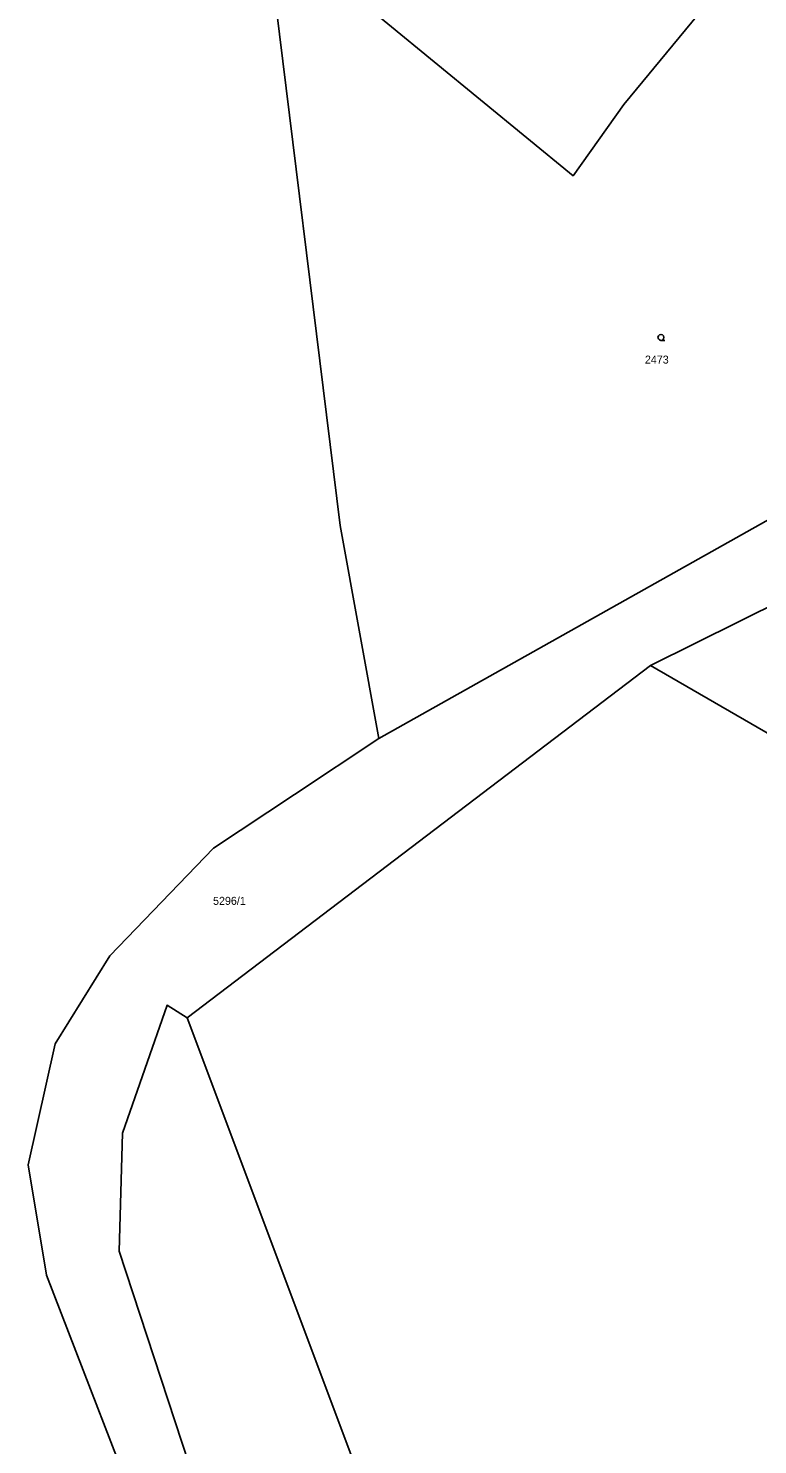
# Model space of a CAD drawing. Extents: x -439750 to -439180, y -1258684 to -1258308.
# Drawn here: x -439666.8 to -439630.4, y -1258510.9 to -1258440.1 of the extents above; entities that cross this region are included whole.
import ezdxf

# ---------------------------------------------------------------- set-up
doc = ezdxf.new("R2010")
doc.units = 0
doc.layers.add('KATASTER', color=7, linetype='Continuous')
doc.layers.add('UOV', color=7, linetype='Continuous')

# ---------------------------------------------------------------- blocks, each defined once
blk = doc.blocks.new('304')
blk.add_lwpolyline([(0, 0), (-0.38, 0.1), (-0.65, 0.37), (-0.75, 0.74), (-0.65, 1.11), (-0.38, 1.38), (-0.01, 1.48), (0.36, 1.38), (0.63, 1.11), (0.73, 0.73), (0.63, 0.35), (0.36, 0.08), (-0.02, -0.02), (0.98, -0.02)])

msp = doc.modelspace()

# ---------------------------------------------------------------- linework, layer by layer
at = {"layer": 'KATASTER'}
for points in [[(-439660.49, -1258516.44), (-439665.91, -1258502.4), (-439666.82, -1258496.88), (-439665.48, -1258490.84), (-439662.74, -1258486.44), (-439657.56, -1258481.06), (-439653.51, -1258478.38), (-439649.29, -1258475.58), (-439627.78, -1258463.49), (-439610.82, -1258457.46), (-439604.91, -1258457.14), (-439594.1, -1258457.31), (-439586.76, -1258455.52), (-439579.1, -1258452.12), (-439572.34, -1258446.7), (-439567.09, -1258440.4), (-439566.51, -1258439.64), (-439564.85, -1258437.53), (-439556.57, -1258427.01), (-439547.65, -1258418.05), (-439537.73, -1258410.35)], [(-439536.05, -1258413.64), (-439546.05, -1258421.31), (-439554.71, -1258430.36), (-439570.11, -1258449.98), (-439574.47, -1258453.63), (-439580.2, -1258456.85), (-439586.86, -1258459.56), (-439593.42, -1258460.84), (-439598.86, -1258460.62), (-439604.63, -1258460.39), (-439610.67, -1258460.8), (-439615.1, -1258461.87), (-439623.26, -1258465.49), (-439629.03, -1258468.61), (-439635.72, -1258471.93), (-439658.88, -1258489.54), (-439659.88, -1258488.91), (-439662.11, -1258495.3), (-439662.28, -1258501.2), (-439658.45, -1258512.88)]]:
    msp.add_lwpolyline(points, dxfattribs=at)
for points in [[(-439654.95, -1258434.81), (-439653.48, -1258436.02), (-439639.58, -1258447.44), (-439637.04, -1258443.88), (-439631.52, -1258437.16), (-439625.47, -1258430.92), (-439614.4, -1258450.89), (-439627.78, -1258463.49), (-439649.29, -1258475.58), (-439651.22, -1258464.92)], [(-439635.72, -1258471.93), (-439629.03, -1258468.61), (-439601.7, -1258475.86), (-439597.79, -1258476.9), (-439591.18, -1258477.49), (-439591.03, -1258485.49), (-439606.15, -1258484.83), (-439620.34, -1258480.81)], [(-439658.88, -1258489.54), (-439635.72, -1258471.93), (-439620.34, -1258480.81), (-439606.15, -1258484.83), (-439591.03, -1258485.49), (-439564.69, -1258504.32), (-439589.36, -1258506.21), (-439597.08, -1258522.38), (-439597.45, -1258561.13), (-439640.46, -1258538.63)]]:
    msp.add_lwpolyline(points, close=True, dxfattribs=at)
at = {"layer": 'UOV'}
for points in [[(-439649.29, -1258475.58), (-439627.78, -1258463.49), (-439618.9, -1258463.55), (-439623.26, -1258465.49), (-439629.03, -1258468.61), (-439635.72, -1258471.93), (-439658.88, -1258489.54), (-439659.88, -1258488.91), (-439662.11, -1258495.3), (-439662.28, -1258501.2), (-439658.45, -1258512.88), (-439640.46, -1258538.63), (-439645.84, -1258537.45), (-439648.8, -1258533.92), (-439660.49, -1258516.44), (-439665.91, -1258502.4), (-439666.82, -1258496.88), (-439665.48, -1258490.84), (-439662.74, -1258486.44), (-439657.56, -1258481.06), (-439653.51, -1258478.38)], [(-439629.03, -1258468.61), (-439597.79, -1258476.9), (-439591.18, -1258477.49), (-439591.03, -1258485.49), (-439606.15, -1258484.83), (-439620.34, -1258480.81), (-439635.72, -1258471.93)]]:
    msp.add_lwpolyline(points, close=True, dxfattribs=at)

# ---------------------------------------------------------------- block references
at = {"layer": 'KATASTER', "xscale": 0.2, "yscale": 0.20000000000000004}
msp.add_blockref('304', (-439635.19, -1258455.67), dxfattribs=at)

# ---------------------------------------------------------------- texts
at = {"layer": 'KATASTER'}
msp.add_text('2473', height=0.4, dxfattribs=at).set_placement((-439635.992, -1258456.83))
at = {"layer": 'UOV'}
msp.add_text('5296/1', height=0.4, dxfattribs=at).set_placement((-439657.584, -1258483.89))

doc.saveas('drawing.dxf')
